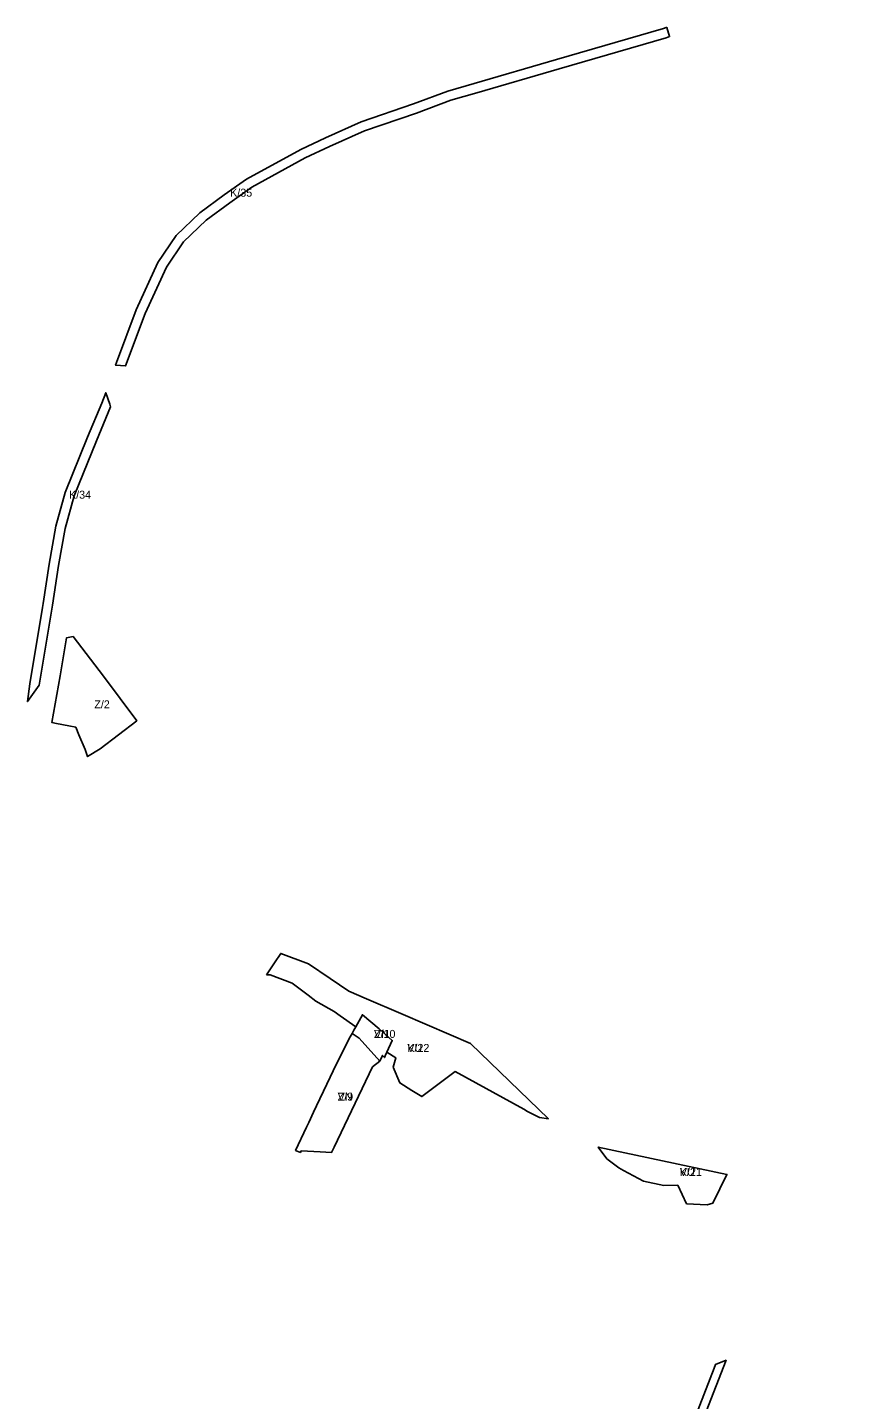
# Model space of a CAD drawing. Extents: x -521969 to -519862, y -1142171 to -1140238.
# Drawn here: x -520372 to -519862, y -1141108 to -1140250 of the extents above; entities that cross this region are included whole.
import ezdxf

# ---------------------------------------------------------------- set-up
doc = ezdxf.new("R2010")
doc.units = 0
for name, color, linetype in [('95420023', 7, 'Continuous'), ('96111023', 7, 'Continuous'), ('96141023', 7, 'Continuous'), ('96202423', 7, 'Continuous')]:
    doc.layers.add(name, color=color, linetype=linetype)

msp = doc.modelspace()

# ---------------------------------------------------------------- linework, layer by layer
at = {"layer": '95420023'}
for points in [[(-520351.39, -1140655.57), (-520347.36, -1140631.75), (-520343.28, -1140631.04), (-520324.4, -1140655.71), (-520303.56, -1140683.6), (-520326.31, -1140701.14), (-520334.3, -1140706.02), (-520335.84, -1140701.48), (-520339.66, -1140692.44), (-520341.7, -1140687.61), (-520345.87, -1140686.81), (-520353.6, -1140685.32), (-520356.53, -1140684.75)], [(-520168.95, -1140879.03), (-520167.79, -1140876.9), (-520166.62, -1140874.78), (-520162.5, -1140867.24), (-520152.09, -1140876.15), (-520143.83, -1140883.35), (-520147.23, -1140890.72), (-520148.27, -1140892.97), (-520148.74, -1140894), (-520149.94, -1140892.73), (-520151.68, -1140896.26), (-520164.55, -1140881.96)], [(-520197.39, -1140937.44), (-520196.08, -1140934.67), (-520193, -1140928.16), (-520191.17, -1140924.29), (-520184.7, -1140910.65), (-520178.74, -1140898.05), (-520170.08, -1140881.1), (-520168.95, -1140879.03), (-520164.55, -1140881.96), (-520151.68, -1140896.26), (-520156.19, -1140899.86), (-520180.26, -1140950.09), (-520181.77, -1140953.24), (-520189.01, -1140952.86), (-520200.79, -1140952.24), (-520201.27, -1140953.32), (-520201.3, -1140953.32), (-520204.29, -1140951.99)]]:
    msp.add_lwpolyline(points, close=True, dxfattribs=at)
at = {"layer": '96111023'}
for points in [[(-520316.15, -1140459.86), (-520303.81, -1140426.86), (-520290.26, -1140397.28), (-520278.94, -1140380.49), (-520264.1, -1140366.33), (-520248.84, -1140355.12), (-520234.9, -1140345.26), (-520200.96, -1140326.65), (-520185.56, -1140319.41), (-520163.36, -1140309.5), (-520130.65, -1140298.32), (-520109.13, -1140290.25), (-520092.7, -1140285.53), (-520041.27, -1140270.53), (-519974.44, -1140251.14), (-519972.61, -1140250.6), (-519972.39, -1140250.5), (-519970.54, -1140256.24), (-519972.75, -1140256.9), (-520039.59, -1140276.29), (-520091.03, -1140291.29), (-520107.24, -1140295.95), (-520128.63, -1140303.97), (-520161.16, -1140315.09), (-520183.06, -1140324.86), (-520198.24, -1140332), (-520231.71, -1140350.36), (-520245.33, -1140359.99), (-520260.24, -1140370.94), (-520274.33, -1140384.38), (-520285.01, -1140400.23), (-520298.27, -1140429.16), (-520310.52, -1140461.93), (-520316.75, -1140461.52)], [(-520370.36, -1140660.47), (-520362.5, -1140612.89), (-520362.06, -1140610.41), (-520358.32, -1140585.75), (-520354.07, -1140562.1), (-520348.31, -1140541.08), (-520334.28, -1140506.54), (-520325.43, -1140485.29), (-520322.93, -1140478.71), (-520320.44, -1140485.82), (-520319.85, -1140487.51), (-520328.73, -1140508.82), (-520342.62, -1140543.01), (-520348.21, -1140563.43), (-520352.4, -1140586.73), (-520356.14, -1140611.39), (-520356.59, -1140613.91), (-520364.42, -1140661.36), (-520371.84, -1140671.63)], [(-520222.55, -1140842.43), (-520217.49, -1140834.9), (-520213.5, -1140828.96), (-520196.23, -1140835.45), (-520182.58, -1140844.72), (-520170.98, -1140852.6), (-520159.88, -1140857.36), (-520138.6, -1140866.49), (-520122.13, -1140873.55), (-520094.9, -1140885.23), (-520046.33, -1140932.29), (-520051.93, -1140931.48), (-520055.67, -1140929.56), (-520059.41, -1140927.64), (-520061.67, -1140926.36), (-520104.55, -1140902.75), (-520125.39, -1140918.45), (-520131.65, -1140914.52), (-520139.09, -1140909.85), (-520143.26, -1140900.05), (-520141.61, -1140894.1), (-520147.23, -1140890.72), (-520143.83, -1140883.35), (-520152.09, -1140876.15), (-520162.5, -1140867.24), (-520166.62, -1140874.78), (-520176.48, -1140867.88), (-520180.27, -1140865.22), (-520191.59, -1140858.73), (-520196.46, -1140855.08), (-520206.43, -1140847.59), (-520220.12, -1140842.45)], [(-519999.3, -1140964.63), (-520002.28, -1140962.91), (-520009.84, -1140957.29), (-520015.17, -1140949.95), (-519934.8, -1140967.08), (-519943.51, -1140985.08), (-519947.03, -1140986.05), (-519959.93, -1140985.31), (-519965.47, -1140973.69), (-519974.08, -1140974.02), (-519986.94, -1140971.3)], [(-519942.77, -1141088.03), (-519941.9, -1141085.78), (-519941.89, -1141085.78), (-519935.26, -1141083.16), (-520002.16, -1141254.73), (-519901.27, -1141289.8), (-519861.86, -1141303.89), (-519864.09, -1141309.46), (-519903.26, -1141295.46), (-520004.78, -1141260.17), (-520007.53, -1141254.06), (-519973.57, -1141167.53)]]:
    msp.add_lwpolyline(points, close=True, dxfattribs=at)
at = {"layer": '96141023'}
for points in [[(-520222.55, -1140842.43), (-520217.49, -1140834.9), (-520213.5, -1140828.96), (-520196.23, -1140835.45), (-520182.58, -1140844.72), (-520170.98, -1140852.6), (-520159.88, -1140857.36), (-520138.6, -1140866.49), (-520122.13, -1140873.55), (-520094.9, -1140885.23), (-520046.33, -1140932.29), (-520051.93, -1140931.48), (-520055.67, -1140929.56), (-520059.41, -1140927.64), (-520061.67, -1140926.36), (-520104.55, -1140902.75), (-520125.39, -1140918.45), (-520131.65, -1140914.52), (-520139.09, -1140909.85), (-520143.26, -1140900.05), (-520141.61, -1140894.1), (-520147.23, -1140890.72), (-520143.83, -1140883.35), (-520152.09, -1140876.15), (-520162.5, -1140867.24), (-520166.62, -1140874.78), (-520176.48, -1140867.88), (-520180.27, -1140865.22), (-520191.59, -1140858.73), (-520196.46, -1140855.08), (-520206.43, -1140847.59), (-520220.12, -1140842.45)], [(-519999.3, -1140964.63), (-520002.28, -1140962.91), (-520009.84, -1140957.29), (-520015.17, -1140949.95), (-519934.8, -1140967.08), (-519943.51, -1140985.08), (-519947.03, -1140986.05), (-519959.93, -1140985.31), (-519965.47, -1140973.69), (-519974.08, -1140974.02), (-519986.94, -1140971.3)]]:
    msp.add_lwpolyline(points, close=True, dxfattribs=at)
at = {"layer": '96202423'}
for points in [[(-520143.83, -1140883.35), (-520147.23, -1140890.72), (-520148.27, -1140892.97), (-520148.74, -1140894), (-520149.94, -1140892.73), (-520151.68, -1140896.26), (-520164.55, -1140881.96), (-520168.95, -1140879.03), (-520167.79, -1140876.9), (-520166.62, -1140874.78), (-520162.5, -1140867.24), (-520152.09, -1140876.15)], [(-520151.68, -1140896.26), (-520156.19, -1140899.86), (-520180.26, -1140950.09), (-520181.77, -1140953.24), (-520189.01, -1140952.86), (-520200.79, -1140952.24), (-520201.27, -1140953.32), (-520201.3, -1140953.32), (-520204.29, -1140951.99), (-520197.39, -1140937.44), (-520196.08, -1140934.67), (-520193, -1140928.16), (-520191.17, -1140924.29), (-520184.7, -1140910.65), (-520178.74, -1140898.05), (-520170.08, -1140881.1), (-520168.95, -1140879.03), (-520164.55, -1140881.96)]]:
    msp.add_lwpolyline(points, close=True, dxfattribs=at)

# ---------------------------------------------------------------- texts
at = {"layer": '95420023'}
for s, p in [('Z/2', (-520330.05, -1140675.88)), ('Z/10', (-520155.27, -1140881.75)), ('Z/9', (-520177.99, -1140920.96))]:
    msp.add_text(s, height=5, rotation=360, dxfattribs=at).set_placement(p)
at = {"layer": '96111023'}
for s, rotation, p in [('K/35', 0, (-520245.16, -1140356.22)), ('K/34', 0, (-520345.85, -1140544.9)), ('K/22', 360, (-520134.44, -1140890.52)), ('K/21', 0, (-519964.15, -1140968))]:
    msp.add_text(s, height=5, rotation=rotation, dxfattribs=at).set_placement(p)
at = {"layer": '96141023'}
for rotation, p in [(360, (-520134.44, -1140890.52)), (0, (-519964.15, -1140968))]:
    msp.add_text('VU', height=5, rotation=rotation, dxfattribs=at).set_placement(p)
at = {"layer": '96202423'}
for p in [(-520155.27, -1140881.75), (-520177.99, -1140920.96)]:
    msp.add_text('VN', height=5, rotation=360, dxfattribs=at).set_placement(p)

doc.saveas('drawing.dxf')
